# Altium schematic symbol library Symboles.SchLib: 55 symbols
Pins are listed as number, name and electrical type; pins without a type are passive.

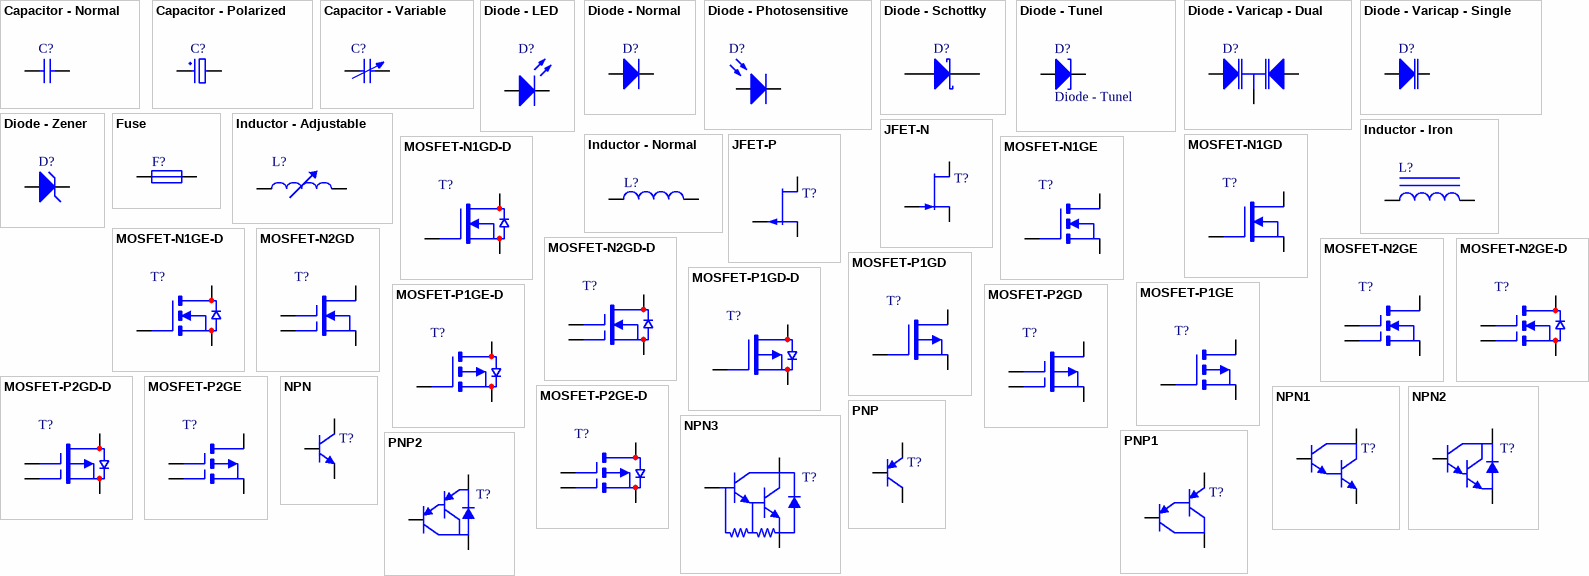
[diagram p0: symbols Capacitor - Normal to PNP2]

## Capacitor - Normal
designator C?  (value not drawn)
Nonpolarized Capacitor
pins: 1, 2

## Capacitor - Polarized
designator C?  (value not drawn)
Polarized Capacitor
pins: 1, 2

## Capacitor - Variable
designator C?  (value not drawn)
Adjustable/Variable Capacitor
pins: 1, 2

## Diode - LED
designator D?  (value not drawn)
Light Emitting Diode
pins: 1 A, 2 K

## Diode - Normal
designator D?  (value not drawn)
Common diode
pins: 1 A, 2 K

## Diode - Photosensitive
designator D?  (value not drawn)
Light Sensing Diode
pins: 1 A, 2 K

## Diode - Schottky
designator D?  (value not drawn)
Schottky Diode
pins: 1 A, 2 K

## Diode - Tunel
designator D?
Tunnel Diode
pins: 1 A, 2 K

## Diode - Varicap - Dual
designator D?  (value not drawn)
Variable Capacitance Diode
pins: 1 A1, 2 A2, 3 K

## Diode - Varicap - Single
designator D?  (value not drawn)
Variable Capacitance Diode
pins: 1 K, 3 A

## Diode - Zener
designator D?  (value not drawn)
Zener Diode
pins: 1 A, 2 K

## Fuse
designator F?  (value not drawn)
Blowing Fuse
pins: 1, 2

## Inductor - Adjustable
designator L?  (value not drawn)
Adjustable Inductor
pins: 1, 2

## Inductor - Iron
designator L?  (value not drawn)
Magnetic-Core Inductor
pins: 1, 2

## Inductor - Normal
designator L?  (value not drawn)
pins: 1, 2

## JFET-N
designator T?  (value not drawn)
N-Channel JFET
pins: 1 D, 2 S, 3 G

## JFET-P
designator T?  (value not drawn)
P-Channel JFET
pins: 1 D, 2 S, 3 G

## MOSFET-N1GD
designator T?  (value not drawn)
MOSFET- N - 1 Gate - Depletion
pins: 1 D, 2 S, 3 G

## MOSFET-N1GD-D
designator T?  (value not drawn)
MOSFET- N - 1 Gate - Depletion
pins: 1 D, 2 S, 3 G

## MOSFET-N1GE
designator T?  (value not drawn)
MOSFET- N - 1 Gate - Enhancement
pins: 1 D, 2 S, 3 G

## MOSFET-N1GE-D
designator T?  (value not drawn)
MOSFET- N - 1 Gate - Enhancement
pins: 1 D, 2 S, 3 G

## MOSFET-N2GD
designator T?  (value not drawn)
MOSFET- N - 2 Gate - Depletion
pins: 1 D, 2 S, 3 G1, 4 G2

## MOSFET-N2GD-D
designator T?  (value not drawn)
MOSFET- N - 2 Gate - Depletion
pins: 1 D, 2 S, 3 G1, 4 G2

## MOSFET-N2GE
designator T?  (value not drawn)
MOSFET- N - 2 Gate - Enhancement
pins: 1 D, 2 S, 3 G1, 4 G2

## MOSFET-N2GE-D
designator T?  (value not drawn)
MOSFET- N - 2 Gate - Enhancement
pins: 1 D, 2 S, 3 G1, 4 G2

## MOSFET-P1GD
designator T?  (value not drawn)
MOSFET- P - 1 Gate - Depletion
pins: 1 G, 2 D, 3 S

## MOSFET-P1GD-D
designator T?  (value not drawn)
MOSFET- P - 1 Gate - Depletion
pins: 1 G, 2 D, 3 S

## MOSFET-P1GE
designator T?  (value not drawn)
MOSFET- P - 1 Gate - Enhancement
pins: 1 G, 2 D, 3 S

## MOSFET-P1GE-D
designator T?  (value not drawn)
MOSFET- P - 1 Gate - Enhancement
pins: 1 G, 2 D, 3 S

## MOSFET-P2GD
designator T?  (value not drawn)
MOSFET- P - 2 Gate - Depletion
pins: 1 G1, 2 G2, 3 D, 4 S

## MOSFET-P2GD-D
designator T?  (value not drawn)
MOSFET- P - 2 Gate - Depletion
pins: 1 G1, 2 G2, 3 D, 4 S

## MOSFET-P2GE
designator T?  (value not drawn)
MOSFET- P - 2 Gate - Enhancement
pins: 1 G1, 2 G2, 3 D, 4 S

## MOSFET-P2GE-D
designator T?  (value not drawn)
MOSFET- P - 2 Gate - Enhancement
pins: 1 G1, 2 G2, 3 D, 4 S

## NPN
designator T?  (value not drawn)
NPN, Bipolar
pins: 1 C, 2 B, 3 E

## NPN1
designator T?
NPN, Darlington, Bipolar
pins: 1 C, 2 B, 3 E

## NPN2
designator T?
NPN, Darlington, Bipolar, with Diode
pins: 1 C, 2 B, 3 E

## NPN3
designator T?
NPN, Darlington, Bipolar, with Diode and Resistors
pins: 1 C, 2 B, 3 E

## PNP
designator T?
PNP, Bipolar
pins: 1 C, 2 B, 3 E

## PNP1
designator T?
PNP, Darlington, Bipolar
pins: 1 E, 2 B, 3 C

## PNP2
designator T?
PNP, Darlington, Bipolar, with Diode
pins: 1 C, 2 B, 3 E

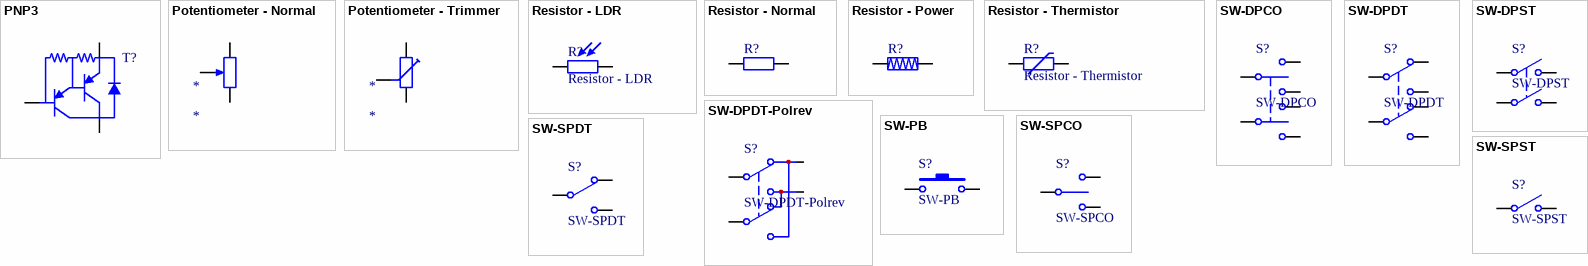
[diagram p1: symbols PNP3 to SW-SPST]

## PNP3
designator T?
PNP, Darlington, Bipolar, with Diode and Resistors
pins: 1 C, 2 B, 3 E

## Potentiometer - Normal
designator *
Adjustable Potentiometer
pins: 1 TOP, 2 BOT, 3 TAP

## Potentiometer - Trimmer
designator *
Trimmer Potentiomerer
pins: 1 TOP, 2 BOT, 3 TAP

## Resistor - LDR
designator R?
Photoresistive Resistor
pins: 1, 2

## Resistor - Normal
designator R?
Normal Resistor
pins: 1, 2

## Resistor - Power
designator R?
Power Resistor
pins: 1, 2

## Resistor - Thermistor
designator R?
Temperature Sensitive Resistor
pins: 1, 2

## SW-DPCO
designator S?
Dual Pole, Center Off
pins: 1, 2, 3, 4, 5, 6

## SW-DPDT
designator S?
Dual Pole, Double Throw
pins: 1, 2, 3, 4, 5, 6

## SW-DPDT-Polrev
designator S?
Dual Pole, Double Throw Polarity Reverser
pins: 1, 2, 3, 4

## SW-DPST
designator S?
Double Pole, Single Throw
pins: 1, 2, 3, 4

## SW-PB
designator S?
Switch
pins: 1, 2

## SW-SPCO
designator S?
Single Pole, Center Off
pins: 1, 2, 3

## SW-SPDT
designator S?
Single Pole, Double Throw
pins: 1, 2, 3

## SW-SPST
designator S?
Single-Pole, Single Throw
pins: 1, 2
